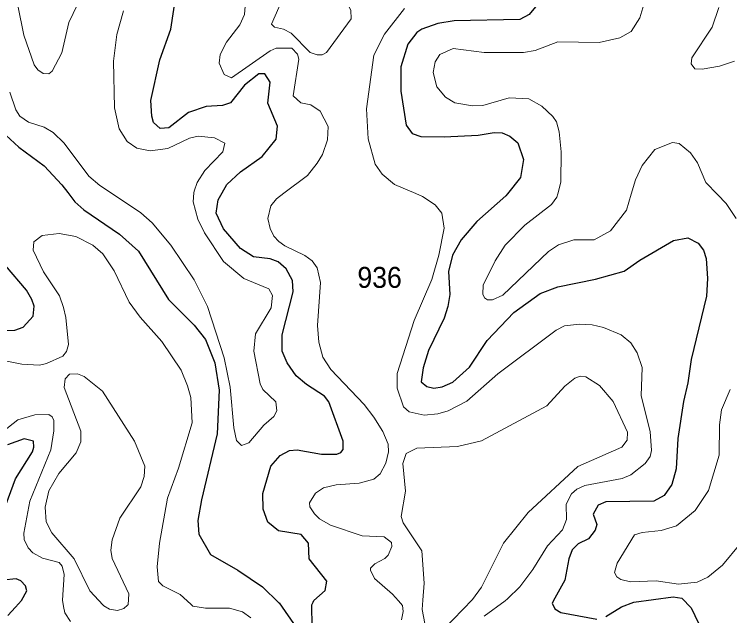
# Model space of a CAD drawing. Extents: x 473.9 to 500, y 7733.1 to 7760.8.
# Drawn here: x 482.142 to 484.875, y 7751.048 to 7753.344 of the extents above; entities that cross this region are included whole.
import ezdxf

# ---------------------------------------------------------------- set-up
doc = ezdxf.new("R2010")
doc.units = 0
doc.header["$LTSCALE"] = 0.032
doc.layers.add('1', color=7, linetype='Continuous', lineweight=25)
doc.layers.add('2', color=7, linetype='Continuous', lineweight=13)
doc.layers.add('21', color=7, linetype='Continuous')

msp = doc.modelspace()

# ---------------------------------------------------------------- linework, layer by layer
at = {"layer": '1'}
for points in [[(483.2793, 7751.005), (483.2784, 7751.0898), (483.2831, 7751.0995), (483.2863, 7751.1062), (483.329, 7751.1445), (483.3355, 7751.1794), (483.2681, 7751.2643), (483.2654, 7751.3243), (483.238, 7751.3584), (483.1519, 7751.3715), (483.1109, 7751.4049), (483.0924, 7751.4551), (483.0913, 7751.5149), (483.122, 7751.6192), (483.1577, 7751.66), (483.1936, 7751.678), (483.2224, 7751.6814), (483.3157, 7751.6646), (483.3736, 7751.6645), (483.3892, 7751.6711), (483.3982, 7751.6826), (483.3977, 7751.7141), (483.3436, 7751.8647), (483.3266, 7751.8856), (483.2578, 7751.9301), (483.2183, 7751.9637), (483.1848, 7752.0138), (483.1659, 7752.0583), (483.1657, 7752.1202), (483.2077, 7752.2845), (483.2044, 7752.3278), (483.18, 7752.3718), (483.1506, 7752.3985), (483.1191, 7752.4104), (483.0562, 7752.4184), (483.0063, 7752.4501), (482.9416, 7752.5253), (482.913, 7752.5846), (482.9208, 7752.635), (482.9358, 7752.6619), (482.9537, 7752.694), (483.0058, 7752.743), (483.0886, 7752.8014), (483.1426, 7752.8667), (483.1472, 7752.917), (483.1111, 7753.0052), (483.1201, 7753.085), (483.0997, 7753.117), (483.0767, 7753.1161), (483.0221, 7753.0732), (482.9684, 7753.0055), (482.937, 7752.9952), (482.8745, 7752.9922), (482.807, 7752.9694), (482.7326, 7752.9101), (482.6989, 7752.9084), (482.674, 7752.9311), (482.667, 7752.9554), (482.6635, 7753.0151), (482.6987, 7753.1699), (482.7407, 7753.2868), (482.763, 7753.4384)], [(484.1389, 7753.3802), (484.1082, 7753.3427), (484.0727, 7753.3242), (483.8225, 7753.3193), (483.7599, 7753.3087), (483.6993, 7753.2877), (483.68, 7753.2749), (483.6458, 7753.2295), (483.619, 7753.1428), (483.6187, 7753.0509), (483.6392, 7752.9201), (483.6617, 7752.8893), (483.6949, 7752.8779), (483.7846, 7752.8755), (483.9134, 7752.8828), (483.9753, 7752.8932), (484.0055, 7752.8915), (484.0351, 7752.8786), (484.0653, 7752.8527), (484.0873, 7752.7895), (484.0753, 7752.7211), (484.0257, 7752.6585), (484.0195, 7752.6507), (483.9083, 7752.5523), (483.849, 7752.4833), (483.8165, 7752.4247), (483.8006, 7752.3614), (483.8052, 7752.2739), (483.7983, 7752.2285), (483.7837, 7752.1837), (483.7242, 7752.0599), (483.7037, 7751.9943), (483.6967, 7751.941), (483.7173, 7751.9231), (483.745, 7751.9163), (483.7768, 7751.9212), (483.8177, 7751.9391), (483.8803, 7751.9963), (483.9488, 7752.0981), (484.0504, 7752.2056), (484.1503, 7752.2777), (484.2188, 7752.3034), (484.362, 7752.3323), (484.4711, 7752.3632), (484.5312, 7752.4057), (484.6596, 7752.4808), (484.7147, 7752.4902), (484.7537, 7752.4702), (484.7745, 7752.4437), (484.7846, 7752.4119), (484.7893, 7752.3352), (484.786, 7752.2674), (484.7278, 7752.026), (484.7151, 7751.9365)], [(482.1096, 7752.8825), (482.16, 7752.8368), (482.2562, 7752.7648), (482.324, 7752.6924), (482.3461, 7752.6637), (482.3736, 7752.6281), (482.4073, 7752.5976), (482.5439, 7752.5051), (482.6168, 7752.4396), (482.731, 7752.2544), (482.8292, 7752.1572), (482.8721, 7752.1024), (482.9086, 7752.0127), (482.9247, 7751.9092), (482.9176, 7751.7422), (482.8574, 7751.4907), (482.8437, 7751.411), (482.8466, 7751.3591), (482.8919, 7751.2818), (482.9958, 7751.2219), (483.0903, 7751.1585), (483.1527, 7751.0973), (483.1534, 7751.0966), (483.2206, 7751.0013)], [(482.086, 7752.1361), (482.1443, 7752.138), (482.1766, 7752.1488), (482.214, 7752.1912), (482.2179, 7752.2291), (482.2098, 7752.2555), (482.189, 7752.2909), (482.1091, 7752.3844)], [(484.7151, 7751.9365), (484.6978, 7751.866), (484.6766, 7751.7242), (484.6703, 7751.6088), (484.6539, 7751.5491), (484.6244, 7751.507), (484.5846, 7751.4856), (484.4017, 7751.4827), (484.372, 7751.4699), (484.3537, 7751.4351), (484.3669, 7751.3961), (484.3613, 7751.3739), (484.3357, 7751.3414), (484.2957, 7751.322), (484.2732, 7751.2999), (484.2606, 7751.2647), (484.2449, 7751.1829), (484.2072, 7751.1151), (484.1961, 7751.0951), (484.2062, 7751.0746), (484.2294, 7751.0596), (484.3673, 7751.0351)], [(482.1109, 7751.4734), (482.1465, 7751.5705), (482.2112, 7751.6731), (482.2172, 7751.6909), (482.2155, 7751.7142), (482.1801, 7751.7226), (482.1162, 7751.7003)], [(482.1171, 7751.0485), (482.1465, 7751.0802), (482.17, 7751.1056), (482.1907, 7751.1422), (482.1854, 7751.162), (482.1678, 7751.1804), (482.1488, 7751.1891), (482.0993, 7751.1836)], [(484.4012, 7751.045), (484.4617, 7751.0819), (484.5082, 7751.0998), (484.6584, 7751.1201), (484.6912, 7751.1144), (484.7272, 7751.078), (484.7555, 7751.0191)]]:
    msp.add_lwpolyline(points, dxfattribs=at)
at = {"layer": '2'}
for points in [[(483.3377, 7753.4258), (483.3119, 7753.4395), (483.2431, 7753.5492), (483.2125, 7753.5797), (483.1929, 7753.5853), (483.153, 7753.5826), (483.1234, 7753.5568), (483.1157, 7753.5128), (483.1531, 7753.3693), (483.124, 7753.3064), (483.1364, 7753.2949), (483.1704, 7753.2868), (483.1998, 7753.2713), (483.2717, 7753.1984), (483.2996, 7753.1889), (483.3183, 7753.1894), (483.3351, 7753.1979), (483.4293, 7753.3271), (483.4279, 7753.3602), (483.4099, 7753.392), (483.393, 7753.4047)], [(482.5157, 7751.3375), (482.545, 7751.4203), (482.6254, 7751.5394), (482.6383, 7751.5796), (482.6413, 7751.6187), (482.6015, 7751.7136), (482.4789, 7751.9045), (482.4088, 7751.9615), (482.3842, 7751.9717), (482.3532, 7751.9699), (482.3367, 7751.9526), (482.3322, 7751.9194), (482.3965, 7751.7517), (482.3965, 7751.712), (482.3781, 7751.6693), (482.3124, 7751.5903), (482.2738, 7751.5244), (482.2599, 7751.4622), (482.2644, 7751.4059), (482.2855, 7751.3647), (482.3713, 7751.2654), (482.4304, 7751.1426), (482.4818, 7751.0874), (482.4841, 7751.0859), (482.5053, 7751.0726), (482.5358, 7751.068), (482.5602, 7751.0755), (482.574, 7751.0874), (482.5766, 7751.0897), (482.5792, 7751.1316), (482.5156, 7751.2657), (482.5107, 7751.2977)]]:
    msp.add_lwpolyline(points, close=True, dxfattribs=at)
for points in [[(483.0285, 7753.4375), (483.0213, 7753.3426), (483.0036, 7753.304), (482.9529, 7753.2381), (482.9288, 7753.1899), (482.9248, 7753.1577), (482.9433, 7753.1135), (482.9722, 7753.1014), (483.1194, 7753.2043), (483.1427, 7753.214), (483.2022, 7753.2148), (483.2239, 7753.1915), (483.2287, 7753.1722), (483.207, 7753.0323), (483.236, 7753.0057), (483.2746, 7752.9977), (483.3099, 7752.9744), (483.3413, 7752.9149), (483.3381, 7752.865), (483.3188, 7752.8088), (483.2995, 7752.775), (483.2617, 7752.7283)], [(482.1561, 7753.3775), (482.1781, 7753.2643), (482.2178, 7753.1509), (482.232, 7753.1315), (482.2529, 7753.1185), (482.2744, 7753.1169), (482.2867, 7753.1267), (482.3241, 7753.1973), (482.3507, 7753.312), (482.3989, 7753.4144)], [(484.5537, 7753.4075), (484.5311, 7753.3298)], [(483.9363, 7751.0463), (484.0175, 7751.1042), (484.0256, 7751.1121), (484.0729, 7751.1581), (484.1228, 7751.224), (484.1791, 7751.3141), (484.2362, 7751.376), (484.2514, 7751.4146), (484.2498, 7751.4741), (484.2699, 7751.5127), (484.2908, 7751.5312), (484.3214, 7751.5448), (484.4645, 7751.5722), (484.4967, 7751.5858), (484.5521, 7751.6292), (484.5706, 7751.6558), (484.5754, 7751.6783), (484.5714, 7751.7507), (484.5369, 7751.8873), (484.5409, 7751.9951), (484.5216, 7752.0514), (484.4975, 7752.0892), (484.4605, 7752.1197), (484.3921, 7752.1478), (484.3487, 7752.1583), (484.3005, 7752.1607), (484.2442, 7752.1543), (484.212, 7752.1382), (483.9885, 7751.9718), (483.8703, 7751.8672), (483.7988, 7751.8303), (483.7602, 7751.819), (483.7071, 7751.8134), (483.6508, 7751.8262), (483.6283, 7751.8455), (483.6042, 7751.9163), (483.605, 7751.9726), (483.6701, 7752.1752), (483.7369, 7752.3312), (483.7642, 7752.4244), (483.7835, 7752.5273), (483.7754, 7752.5852), (483.7497, 7752.6166), (483.7007, 7752.6487), (483.6755, 7752.6596), (483.5946, 7752.6946), (483.5471, 7752.734), (483.5206, 7752.7718), (483.494, 7752.8682), (483.4876, 7752.9824), (483.5149, 7753.1882), (483.5559, 7753.2686), (483.6331, 7753.3659)], [(484.8332, 7753.3694), (484.8077, 7753.2943), (484.7298, 7753.1775), (484.7275, 7753.1549), (484.741, 7753.1362), (484.7699, 7753.1344), (484.8353, 7753.1458), (484.8926, 7753.1654)], [(482.9907, 7751.7169), (483.0096, 7751.6973), (483.0385, 7751.7076), (483.0953, 7751.7756), (483.1337, 7751.8077), (483.1449, 7751.8306), (483.1408, 7751.8639), (483.0912, 7751.9115), (483.0808, 7751.9328), (483.0567, 7752.0583), (483.064, 7752.1235), (483.1239, 7752.2228), (483.1287, 7752.2709), (483.1145, 7752.2963), (483.0187, 7752.3356), (482.9412, 7752.4006), (482.869, 7752.5099), (482.8433, 7752.5615), (482.8259, 7752.6276), (482.8283, 7752.6622), (482.8287, 7752.6687), (482.8406, 7752.7015), (482.8705, 7752.7471), (482.9392, 7752.8194), (482.9464, 7752.8515), (482.9067, 7752.8725), (482.8451, 7752.8786), (482.8115, 7752.8715), (482.7283, 7752.8315), (482.6608, 7752.8232), (482.6104, 7752.8322), (482.5732, 7752.8578), (482.5423, 7752.9067), (482.5252, 7752.9867), (482.5212, 7753.1645), (482.534, 7753.2664), (482.5597, 7753.3577)], [(484.5311, 7753.3298), (484.4977, 7753.2787), (484.4554, 7753.2542), (484.376, 7753.2365), (484.2186, 7753.2386), (484.1317, 7753.2061), (484.0874, 7753.1977), (483.9362, 7753.1985), (483.8187, 7753.2131), (483.7672, 7753.1909), (483.7492, 7753.163), (483.7418, 7753.1215), (483.7559, 7753.0666), (483.7888, 7753.0271), (483.825, 7753.0063), (483.8922, 7752.9938), (483.9314, 7752.9953), (484.032, 7753.0246), (484.1068, 7753.021), (484.1573, 7752.9936), (484.1994, 7752.954), (484.2129, 7752.9334), (484.2232, 7752.8955), (484.2312, 7752.819), (484.2296, 7752.7026), (484.2178, 7752.6579), (484.2145, 7752.6453), (484.1937, 7752.618), (484.0916, 7752.5383), (484.017, 7752.4624), (483.9784, 7752.4029), (483.9327, 7752.3098), (483.9314, 7752.2751), (483.9375, 7752.2613), (483.9499, 7752.2542), (483.9691, 7752.2541), (484.0083, 7752.2713), (484.1831, 7752.4388), (484.221, 7752.4634), (484.2789, 7752.4829), (484.3574, 7752.4833), (484.4188, 7752.5172), (484.4803, 7752.5962), (484.4984, 7752.6571), (484.5147, 7752.712), (484.5408, 7752.7672), (484.5891, 7752.8278), (484.656, 7752.8543), (484.6813, 7752.8508), (484.7249, 7752.8151), (484.7522, 7752.7765), (484.7838, 7752.7014), (484.8274, 7752.6561), (484.8605, 7752.6216), (484.8994, 7752.5642)], [(482.1258, 7753.0466), (482.1483, 7752.9791), (482.1629, 7752.9554), (482.1968, 7752.9315), (482.2567, 7752.9131), (482.2911, 7752.8923), (482.333, 7752.8514), (482.4274, 7752.7255), (482.4693, 7752.6902), (482.51, 7752.6632), (482.626, 7752.5863), (482.669, 7752.5474), (482.7406, 7752.4629), (482.8298, 7752.3295), (482.8802, 7752.228), (482.944, 7752.032), (482.9664, 7751.92), (482.9803, 7751.765), (482.9907, 7751.7169)], [(483.2617, 7752.7283), (483.1719, 7752.6612), (483.1435, 7752.6399), (483.1226, 7752.6126), (483.1105, 7752.5643), (483.1194, 7752.5257), (483.1338, 7752.4968), (483.1523, 7752.4767), (483.1749, 7752.4598), (483.252, 7752.4236), (483.2802, 7752.4027), (483.2995, 7752.3762), (483.3123, 7752.3199), (483.3003, 7752.1559), (483.3051, 7752.0916), (483.3204, 7752.0353), (483.3509, 7751.9878), (483.478, 7751.8544), (483.5158, 7751.8053), (483.5503, 7751.7507), (483.5704, 7751.7024), (483.572, 7751.6735), (483.5608, 7751.6301), (483.5391, 7751.5899), (483.5158, 7751.5689), (483.4595, 7751.5537), (483.371, 7751.548), (483.3228, 7751.536), (483.2922, 7751.5151), (483.2697, 7751.4789), (483.2713, 7751.4636), (483.289, 7751.4363), (483.3083, 7751.4178), (483.3501, 7751.3929), (483.4707, 7751.3527), (483.5544, 7751.3494), (483.5833, 7751.3277), (483.5841, 7751.3117), (483.5704, 7751.2795), (483.5576, 7751.2658), (483.519, 7751.2457), (483.5029, 7751.2297), (483.5029, 7751.2216), (483.5182, 7751.1894), (483.5873, 7751.1299), (483.6094, 7751.105), (483.6251, 7751.0873), (483.6275, 7751.064), (483.6211, 7751.0319)], [(483.0454, 7751.0399), (483.0132, 7751.0624), (482.9642, 7751.0761), (482.8725, 7751.0761), (482.8243, 7751.0841), (482.8163, 7751.0916), (482.7761, 7751.1292), (482.7101, 7751.1613), (482.6924, 7751.179), (482.6876, 7751.2345), (482.6965, 7751.3245), (482.727, 7751.4966), (482.7696, 7751.6108), (482.8219, 7751.7844), (482.8171, 7751.8809), (482.8042, 7751.9259), (482.7801, 7751.9854), (482.7053, 7752.0948), (482.6233, 7752.1872), (482.5815, 7752.2443), (482.5236, 7752.3649), (482.4802, 7752.4293), (482.4416, 7752.4622), (482.3773, 7752.496), (482.313, 7752.5072), (482.2486, 7752.4992), (482.2173, 7752.4751), (482.214, 7752.4437), (482.2534, 7752.3601), (482.3154, 7752.2685), (482.3298, 7752.225), (482.3395, 7752.1864), (482.3491, 7752.0835), (482.3419, 7752.0562), (482.3274, 7752.0393), (482.2647, 7752.0104), (482.239, 7752.0047)], [(482.239, 7752.0047), (482.1714, 7752.0079), (482.1007, 7752.0216)], [(483.781, 7750.9949), (483.8918, 7751.1098), (483.8919, 7751.1099), (483.9262, 7751.1567), (484.0102, 7751.3244), (484.1046, 7751.4415), (484.2943, 7751.617), (484.4623, 7751.6918), (484.4828, 7751.7181), (484.4847, 7751.749), (484.4298, 7751.8657), (484.3778, 7751.9266), (484.3254, 7751.9604), (484.3036, 7751.9622), (484.2832, 7751.9553), (484.2453, 7751.9238), (484.1756, 7751.8486), (483.9267, 7751.7157), (483.8346, 7751.6932), (483.6797, 7751.6872), (483.6385, 7751.6667), (483.6259, 7751.6295), (483.637, 7751.5237), (483.6193, 7751.4268), (483.6272, 7751.4021), (483.6984, 7751.296), (483.7071, 7751.1722), (483.7021, 7751.1066), (483.6994, 7751.0709), (483.7107, 7751.0179)], [(484.8767, 7751.9108), (484.8438, 7751.8336), (484.8358, 7751.7763), (484.8341, 7751.6605), (484.7935, 7751.5261), (484.7431, 7751.4489), (484.6712, 7751.391), (484.6133, 7751.3734), (484.5402, 7751.366), (484.5115, 7751.356), (484.4451, 7751.2484), (484.4348, 7751.2125), (484.4429, 7751.1968), (484.4591, 7751.1858), (484.4959, 7751.1776), (484.5933, 7751.1806), (484.6785, 7751.1684), (484.75, 7751.1764), (484.7912, 7751.1948), (484.8476, 7751.2413), (484.9823, 7751.4038)], [(481.9753, 7751.6542), (482.1554, 7751.7957), (482.2213, 7751.8142), (482.2744, 7751.8166), (482.2864, 7751.8069), (482.2928, 7751.7925), (482.2928, 7751.7539), (482.2816, 7751.6815), (482.202, 7751.4853), (482.1787, 7751.3631), (482.1803, 7751.339), (482.1948, 7751.3068), (482.2132, 7751.2876), (482.2502, 7751.2674), (482.313, 7751.2514), (482.325, 7751.2369), (482.3322, 7751.2055), (482.3266, 7751.1075), (482.3307, 7751.0833), (482.3347, 7751.0592), (482.3572, 7751.0262)]]:
    msp.add_lwpolyline(points, dxfattribs=at)

# ---------------------------------------------------------------- texts
at = {"layer": '21', "width": 0.95}
msp.add_text('936', height=0.08, dxfattribs=at).set_placement((483.4527, 7752.2995))

doc.saveas('drawing.dxf')
